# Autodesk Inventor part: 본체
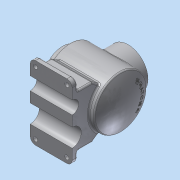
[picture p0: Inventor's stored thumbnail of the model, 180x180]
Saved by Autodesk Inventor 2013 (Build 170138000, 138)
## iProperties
Created: 2018-08
Part Number: 본체
Material: 알루미늄 6061
Document SubType Name: Modeling
Designer: Administrator
Density: 2.71 g/cm^3
Mass: 1972.6 g
Surface Area: 1152.1 cm^2
Volume: 727.898 cm^3
Author: Administrator
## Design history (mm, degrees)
sketch "스케치2"
  geometry: L1 (-50, -50)-(48, -50); L2 (48, -50)-(48, 0); L3 (53.85, 56.094)-(-48, -50); L4 (-54, 54)-(50, -50); L5 (48, 0)-(-90.918, 0); L6 (50, 0)-(48, 0); A1 r 116 centre (54.671, 0) between (-61.329, 0) and (-50, -50); 1 further point
  constraints: 12 end point, 3 point on line, 2 perpendicular, 2 point on circle, 1 centre point
  dimensions: "d2" = 116 radius of A1; "d109" = 98 distance of L1.start L1.end; "d110" = 50 distance of L1.end L2.end; "d114" = 2 distance of L6.start L6.end
revolve "회전1" sketch "스케치2" stored, may be unused: angle "d3" = 90 deg
feature "쉘1" dims "d4" = 10
node "작업 평면1"
sketch "스케치3"
  geometry: C1 r 50 at (0, 0); 1 further point
  constraints: 1 centre point, 1 coincident
  dimensions: "d6" = 100 diameter of C1
extrude "돌출1" join sketch "스케치3" distance "d7" = 16; taper "d8" = 0 deg
sketch "스케치4"
  geometry: C1 r 50 at (0, 0) reference; C2 r 38 at (0, 0)
  constraints: 1 centre point, 1 coincident
  dimensions: "d9" = 76 diameter of C2
extrude "돌출2" join sketch "스케치4" distance "d10" = 12; taper "d11" = 0 deg
sketch "스케치5"
  geometry: C1 r 38 at (0, 0) reference; C2 r 27 at (0, 0)
  constraints: 1 centre point, 1 coincident
  dimensions: "d12" = 54 diameter of C2
extrude "돌출3" cut sketch "스케치5" distance "d13" = 22; taper "d14" = 0 deg
sketch "스케치6"
  geometry: C1 r 27 at (0, 0) reference; C2 r 40 at (0, 0)
  constraints: 1 centre point, 1 coincident
  dimensions: "d15" = 80 diameter of C2
extrude "돌출4" cut sketch "스케치6" distance "d16" = 50; taper "d17" = 0 deg
node "작업 평면2"
sketch "스케치7"
  geometry: C1 r 38 at (0, 0); 1 further point
  constraints: 1 centre point, 1 coincident
  dimensions: "d19" = 76 diameter of C1
extrude "돌출5" join sketch "스케치7" stored distance "d20" = 50; taper "d21" = 0 deg
sketch "스케치8"
  geometry: C1 r 38 at (0, 0) reference; C2 r 27 at (0, 0)
  constraints: 1 centre point, 1 coincident
  dimensions: "d22" = 54 diameter of C2
extrude "돌출6" cut sketch "스케치8" distance "d23" = 50; taper "d24" = 0 deg
sketch "스케치9"
  geometry: L1 (65, -38)-(32.496, -38) reference; L2 (32.496, 38)-(65, 38) reference; L3 (65, 38)-(65, 27) reference; L4 (65, 27)-(29.513, 27) reference; L5 (29.513, -27)-(65, -27) reference; L6 (65, -27)-(65, -38) reference; L7 (-50, 0)-(-82, 0); L8 (-82, 0)-(-82, -70); L9 (-82, -70)-(-72, -70); L10 (-72, -70)-(-72, -50); L11 (-43.437, -50)-(-29.59, -40.304); L12 (-72, -70)-(-16.21, -70); L13 (-72, -50)-(-43.437, -50); L14 (-50, 0)-(-29.59, -40.304); A1 r 50 centre (0, 0) between (32.496, 38) and (32.496, -38) reference; A2 r 40 centre (0, 0) between (29.513, 27) and (29.513, -27) reference; 1 further point
  constraints: 16 end point, 3 perpendicular, 2 parallel, 2 point on circle, 1 horizontal
  dimensions: "d25" = 82 distance of A2.centre L7.end; "d26" = 70 distance of L7.end L8.end; "d27" = 10 distance of L8.end L9.end; "d28" = 20 distance of L9.end L10.end; "d29" = 35 deg angle of L12 L11
extrude "돌출7" join sketch "스케치9" stored distance "d30" = 80; taper "d31" = 0 deg
sketch "스케치10"
  geometry: L1 (-70, -82)-(70, -82) reference; L2 (0, -82)-(27.5, -82); L3 (0, -82)-(-22.5, -82); C1 r 12.5 at (27.5, -82); C2 r 17.5 at (-22.5, -82)
  constraints: 4 end point, 2 centre point, 2 coincident, 2 point on line, 1 midpoint
  dimensions: "d32" = 27.5 distance of L2.start L2.end; "d33" = 25 diameter of C1; "d34" = 22.5 distance of L2.start L3.end; "d35" = 35 diameter of C2
extrude "돌출8" cut sketch "스케치10" stored distance "d36" = 80; taper "d37" = 0 deg
sketch "스케치11" dims "d38" = 65
  geometry: C1 r 38 at (0, 0) reference; 2 further points
  constraints: 1 coincident, 1 horizontal alignment, 2 other
hole "구멍1" sketch "스케치11" at (32.5, 0) diameter "d39" = 3.459; stored, may be unused: countersink angle "d43" = 90 deg, drill point angle "d45" = 118 deg; dims "d40" = 8, "d41" = 4, "d42" = 2, "d44" = 10
sketch "스케치12" dims "d49" = 65
  geometry: C1 r 38 at (0, 0) reference; 2 further points
  constraints: 1 coincident, 1 horizontal alignment, 2 other
hole "구멍2" sketch "스케치12" at (32.5, 0) diameter "d50" = 3.459; stored, may be unused: countersink angle "d54" = 90 deg, drill point angle "d56" = 118 deg; dims "d51" = 8, "d52" = 4, "d53" = 2, "d55" = 10
fillet "모깎기1" dims "d60" = 10
hole "구멍3" diameter "d63" = 8; stored, may be unused: countersink angle "d67" = 90 deg, drill point angle "d69" = 0 deg; dims "d61" = 10, "d62" = 10, "d64" = 8, "d65" = 4, "d66" = 2, "d68" = 10
hole "구멍4" diameter "d72" = 8; stored, may be unused: countersink angle "d76" = 90 deg, drill point angle "d78" = 0 deg; dims "d70" = 10, "d71" = 10, "d73" = 8, "d74" = 4, "d75" = 2, "d77" = 10
hole "구멍5" diameter "d81" = 8; stored, may be unused: countersink angle "d85" = 90 deg, drill point angle "d87" = 0 deg; dims "d79" = 10, "d80" = 10, "d82" = 8, "d83" = 4, "d84" = 2, "d86" = 10
hole "구멍6" diameter "d90" = 8; stored, may be unused: countersink angle "d94" = 90 deg, drill point angle "d96" = 0 deg; dims "d88" = 10, "d89" = 10, "d91" = 8, "d92" = 4, "d93" = 2, "d95" = 10
node "작업 평면3"
sketch "스케치13"
  geometry: C1 r 32.5 at (0, 0); 1 further point
  constraints: 1 centre point, 1 coincident, 1 other
  dimensions: "d98" = 65 diameter of C1
fillet "모깎기2" dims "d101" = 3
fillet "모깎기3" dims "d102" = 3
fillet "모깎기4" dims "d103" = 3
fillet "모깎기5" dims "d104" = 3
fillet "모깎기6" dims "d105" = 3
chamfer "모따기1" distance "d106" = 1; stored, may be unused: second distance "d107" = 2, angle "d108" = 45 deg
feature "엠보싱2" dims "d2" = 116, "d109" = 98, "d110" = 50, "d111" = 0.5, "d112" = 0
node "솔리드1"
mirror "대칭1"
pattern_circular "원형 패턴1" dims angle "d47" = 360 deg
pattern_circular "원형 패턴2" dims angle "d58" = 360 deg
node "절단 모서리 투영1"
other parameters: "d5" = -16, "d18" = 65, "d97" = 55
